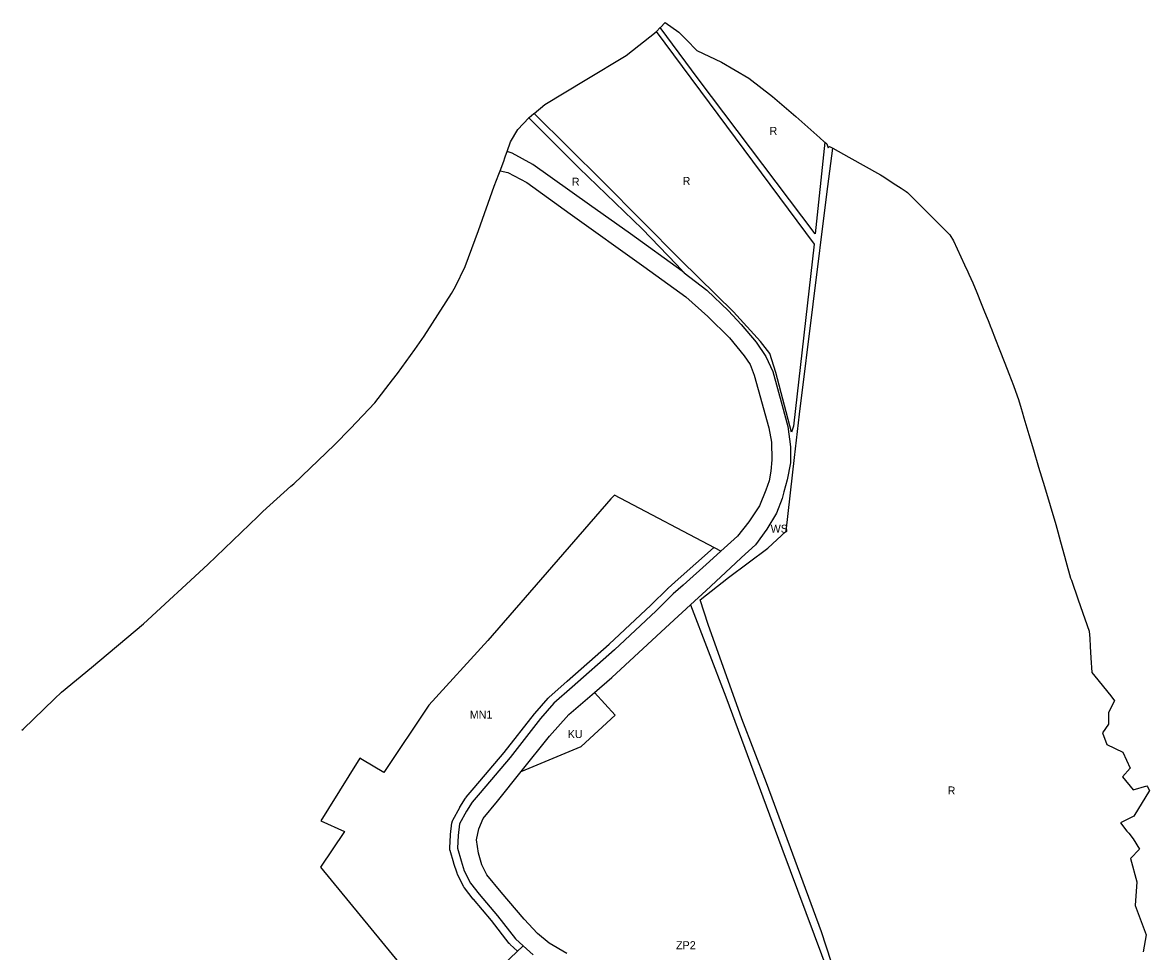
# Model space of a CAD drawing. Extents: x 7435758 to 7439981, y 5550649 to 5554049.
# Drawn here: x 7439107 to 7439840, y 5553445 to 5554049 of the extents above; entities that cross this region are included whole.
import ezdxf

# ---------------------------------------------------------------- set-up
doc = ezdxf.new("R2010")
doc.units = 0
for name, color, linetype in [('linie_rozgraniczające', 7, 'Continuous'), ('linie_zabudowy_nieprzekraczalne', 7, 'Continuous'), ('oznaczenia_przeznaczen', 7, 'Continuous')]:
    doc.layers.add(name, color=color, linetype=linetype)

msp = doc.modelspace()

# ---------------------------------------------------------------- linework, layer by layer
at = {"layer": 'linie_rozgraniczające'}
for p, q in [((7439519.4, 5554043.4), (7439521.89, 5554045.92)), ((7439521.89, 5554045.92), (7439521.96, 5554045.99)), ((7439546.56, 5554012.59), (7439521.89, 5554045.92)), ((7439521.96, 5554045.99), (7439525.14, 5554049.18)), ((7439525.14, 5554049.18), (7439533.95, 5554042.82)), ((7439499.63, 5554027.77), (7439519.15, 5554043.21)), ((7439519.15, 5554043.21), (7439519.29, 5554043.32)), ((7439519.29, 5554043.32), (7439519.4, 5554043.4)), ((7439519.29, 5554043.32), (7439621.8, 5553905.08)), ((7439533.95, 5554042.82), (7439538.84, 5554037.85)), ((7439538.84, 5554037.85), (7439545.59, 5554030.97)), ((7439545.59, 5554030.97), (7439561.7, 5554023.33)), ((7439473.16, 5554011.71), (7439499.63, 5554027.77)), ((7439561.7, 5554023.33), (7439579.49, 5554012.9)), ((7439446.82, 5553995.88), (7439473.16, 5554011.71)), ((7439622.59, 5553911.85), (7439546.56, 5554012.59)), ((7439579.49, 5554012.9), (7439594.73, 5554001.11)), ((7439594.73, 5554001.11), (7439609.96, 5553988.05)), ((7439439.82, 5553990.08), (7439446.82, 5553995.88)), ((7439429.27, 5553979.59), (7439436.46, 5553987.29)), ((7439436.46, 5553987.29), (7439436.49, 5553987.32)), ((7439436.46, 5553987.29), (7439469.19, 5553954.53)), ((7439436.49, 5553987.32), (7439436.68, 5553987.47)), ((7439436.68, 5553987.47), (7439439.73, 5553990.01)), ((7439439.73, 5553990.01), (7439439.82, 5553990.08)), ((7439484.6, 5553945.76), (7439439.82, 5553990.08)), ((7439609.96, 5553988.05), (7439617.71, 5553981.16)), ((7439424.63, 5553971.66), (7439429.27, 5553979.59)), ((7439617.71, 5553981.16), (7439625.47, 5553974.27)), ((7439422.39, 5553965.32), (7439424.63, 5553971.66)), ((7439628.73, 5553971.37), (7439622.59, 5553911.85)), ((7439625.47, 5553974.27), (7439628.49, 5553971.59)), ((7439628.49, 5553971.59), (7439628.73, 5553971.37)), ((7439628.73, 5553971.37), (7439630.05, 5553970.2)), ((7439421.38, 5553962.48), (7439422.39, 5553965.32)), ((7439425.72, 5553964.3), (7439422.39, 5553965.32)), ((7439439.05, 5553956.76), (7439425.72, 5553964.3)), ((7439630.05, 5553970.2), (7439630.97, 5553967.79)), ((7439630.05, 5553937.66), (7439634.03, 5553967.46)), ((7439630.97, 5553967.79), (7439631.91, 5553968.65)), ((7439631.91, 5553968.65), (7439634.03, 5553967.46)), ((7439634.03, 5553967.46), (7439644.42, 5553961.63)), ((7439417.73, 5553952.83), (7439420.11, 5553959.07)), ((7439420.11, 5553959.07), (7439420.94, 5553961.24)), ((7439420.94, 5553961.24), (7439421.38, 5553962.48)), ((7439475.93, 5553930.52), (7439439.05, 5553956.76)), ((7439644.42, 5553961.63), (7439664.95, 5553950.11)), ((7439413.89, 5553942.79), (7439416.9, 5553950.66)), ((7439416.9, 5553950.66), (7439417.73, 5553952.83)), ((7439417.73, 5553952.83), (7439422.85, 5553951.68)), ((7439422.85, 5553951.68), (7439435.1, 5553945.14)), ((7439469.19, 5553954.53), (7439510.12, 5553915.08)), ((7439664.95, 5553950.11), (7439667.1, 5553948.9)), ((7439403.68, 5553913.88), (7439413.89, 5553942.79)), ((7439435.1, 5553945.14), (7439463.28, 5553924.67)), ((7439535.22, 5553894.66), (7439484.6, 5553945.76)), ((7439667.1, 5553948.9), (7439673.33, 5553944.76)), ((7439673.33, 5553944.76), (7439678.47, 5553941.35)), ((7439612.46, 5553794.49), (7439630.05, 5553937.66)), ((7439678.47, 5553941.35), (7439681.73, 5553939.18)), ((7439681.73, 5553939.18), (7439682.57, 5553938.63)), ((7439682.57, 5553938.63), (7439684.76, 5553936.42)), ((7439684.76, 5553936.42), (7439691.39, 5553929.78)), ((7439502.48, 5553911.8), (7439475.93, 5553930.52)), ((7439691.39, 5553929.78), (7439694.7, 5553926.47)), ((7439463.28, 5553924.67), (7439511.29, 5553890.41)), ((7439694.7, 5553926.47), (7439710.07, 5553911.06)), ((7439395.12, 5553890.51), (7439403.68, 5553913.88)), ((7439510.12, 5553915.08), (7439532.32, 5553891.88)), ((7439536.02, 5553887.38), (7439502.48, 5553911.8)), ((7439710.07, 5553911.06), (7439712.48, 5553907.19)), ((7439712.48, 5553907.19), (7439719.66, 5553891.52)), ((7439621.8, 5553905.08), (7439608.35, 5553786.71)), ((7439388.8, 5553877.51), (7439395.12, 5553890.51)), ((7439532.32, 5553891.88), (7439537.31, 5553886.39)), ((7439569.55, 5553860.97), (7439535.22, 5553894.66)), ((7439719.66, 5553891.52), (7439721.74, 5553887.01)), ((7439511.29, 5553890.41), (7439538.4, 5553870.68)), ((7439537.31, 5553886.39), (7439536.02, 5553887.38)), ((7439537.31, 5553886.39), (7439552.15, 5553875.01)), ((7439721.74, 5553887.01), (7439722.41, 5553885.54)), ((7439722.41, 5553885.54), (7439725.04, 5553879.79)), ((7439386.28, 5553872.98), (7439388.8, 5553877.51)), ((7439725.04, 5553879.79), (7439727.58, 5553873.54)), ((7439373.74, 5553853.58), (7439386.28, 5553872.98)), ((7439538.4, 5553870.68), (7439552.72, 5553857.97)), ((7439552.15, 5553875.01), (7439566.11, 5553861.64)), ((7439727.58, 5553873.54), (7439730.41, 5553866.54)), ((7439566.11, 5553861.64), (7439574.54, 5553852.87)), ((7439730.41, 5553866.54), (7439732.68, 5553860.93)), ((7439552.72, 5553857.97), (7439566.82, 5553844.22)), ((7439586.98, 5553841.83), (7439569.55, 5553860.97)), ((7439732.68, 5553860.93), (7439734.35, 5553856.81)), ((7439734.35, 5553856.81), (7439734.96, 5553855.31)), ((7439734.96, 5553855.31), (7439736.77, 5553850.85)), ((7439368.39, 5553845.29), (7439373.74, 5553853.58)), ((7439574.54, 5553852.87), (7439584.13, 5553841.28)), ((7439736.77, 5553850.85), (7439736.95, 5553850.38)), ((7439736.95, 5553850.38), (7439739.81, 5553843.08)), ((7439362.27, 5553836.63), (7439368.39, 5553845.29)), ((7439566.82, 5553844.22), (7439576.41, 5553832.37)), ((7439584.13, 5553841.28), (7439590.5, 5553831.9)), ((7439592.97, 5553833.92), (7439586.98, 5553841.83)), ((7439739.81, 5553843.08), (7439742.22, 5553836.88)), ((7439351.15, 5553820.9), (7439362.27, 5553836.63)), ((7439576.41, 5553832.37), (7439580.29, 5553826.79)), ((7439590.5, 5553831.9), (7439595.06, 5553822.18)), ((7439597.01, 5553821.68), (7439592.97, 5553833.92)), ((7439742.22, 5553836.88), (7439745.8, 5553827.73)), ((7439580.29, 5553826.79), (7439582.91, 5553819.87)), ((7439745.8, 5553827.73), (7439748.36, 5553821.01)), ((7439347.92, 5553816.72), (7439351.15, 5553820.9)), ((7439582.91, 5553819.87), (7439585.51, 5553810.47)), ((7439595.06, 5553822.18), (7439601.03, 5553800.16)), ((7439607.09, 5553782.76), (7439597.01, 5553821.68)), ((7439748.36, 5553821.01), (7439751.4, 5553813.02)), ((7439336.46, 5553801.91), (7439347.92, 5553816.72)), ((7439585.51, 5553810.47), (7439592.51, 5553785.49)), ((7439751.4, 5553813.02), (7439753.88, 5553806.49)), ((7439753.88, 5553806.49), (7439754.64, 5553803.98)), ((7439754.64, 5553803.98), (7439756.4, 5553798.06)), ((7439320.65, 5553785.12), (7439336.46, 5553801.91)), ((7439601.03, 5553800.16), (7439604.71, 5553786.5)), ((7439756.4, 5553798.06), (7439757.05, 5553795.89)), ((7439757.05, 5553795.89), (7439758.17, 5553792.12)), ((7439609, 5553766.36), (7439612.46, 5553794.49)), ((7439758.17, 5553792.12), (7439761.41, 5553781.26)), ((7439310.14, 5553774.46), (7439320.65, 5553785.12)), ((7439592.51, 5553785.49), (7439594.19, 5553776.18)), ((7439604.71, 5553786.5), (7439606.55, 5553773.29)), ((7439608.35, 5553786.71), (7439607.09, 5553782.76)), ((7439761.41, 5553781.26), (7439764.41, 5553771.18)), ((7439283.64, 5553749.23), (7439310.14, 5553774.46)), ((7439594.19, 5553776.18), (7439594.4, 5553764.73)), ((7439606.55, 5553773.29), (7439606.45, 5553762.87)), ((7439603.68, 5553718.48), (7439609, 5553766.36)), ((7439764.41, 5553771.18), (7439767.7, 5553760.1)), ((7439594.4, 5553764.73), (7439593.65, 5553757.4)), ((7439606.45, 5553762.87), (7439604.3, 5553751.84)), ((7439767.7, 5553760.1), (7439771.48, 5553747.34)), ((7439593.65, 5553757.4), (7439592.6, 5553751.11)), ((7439604.3, 5553751.84), (7439602.24, 5553743.95)), ((7439263.63, 5553731.15), (7439281.86, 5553747.62)), ((7439281.86, 5553747.62), (7439283.64, 5553749.23)), ((7439590.51, 5553745.03), (7439586.36, 5553734.84)), ((7439592.6, 5553751.11), (7439590.51, 5553745.03)), ((7439771.48, 5553747.34), (7439775.22, 5553735.04)), ((7439489.79, 5553739.37), (7439409.89, 5553647.18)), ((7439492.1, 5553741.8), (7439489.79, 5553739.37)), ((7439561.24, 5553705.31), (7439492.1, 5553741.8)), ((7439601.14, 5553739.73), (7439597.49, 5553730.08)), ((7439602.24, 5553743.95), (7439601.14, 5553739.73)), ((7439260.4, 5553728.02), (7439263.63, 5553731.15)), ((7439586.36, 5553734.84), (7439579.49, 5553724.4)), ((7439597.49, 5553730.08), (7439591.15, 5553719.66)), ((7439775.22, 5553735.04), (7439778.96, 5553722.72)), ((7439227.86, 5553696.6), (7439260.4, 5553728.02)), ((7439579.49, 5553724.4), (7439572.05, 5553715.24)), ((7439778.96, 5553722.72), (7439780.27, 5553717.91)), ((7439572.05, 5553715.24), (7439561.24, 5553705.31)), ((7439591.15, 5553719.66), (7439583.74, 5553709.47)), ((7439591.73, 5553707.36), (7439603.68, 5553718.48)), ((7439780.27, 5553717.91), (7439782.01, 5553711.49)), ((7439566.28, 5553688.26), (7439591.73, 5553707.36)), ((7439583.74, 5553709.47), (7439574.72, 5553701.18)), ((7439782.01, 5553711.49), (7439784.56, 5553702.05)), ((7439561.24, 5553705.31), (7439553.97, 5553698.62)), ((7439574.72, 5553701.18), (7439570.69, 5553697.48)), ((7439784.56, 5553702.05), (7439785.45, 5553698.93)), ((7439186.11, 5553658.17), (7439227.86, 5553696.6)), ((7439553.97, 5553698.62), (7439536.7, 5553683.26)), ((7439570.69, 5553697.48), (7439551.61, 5553679.77)), ((7439785.45, 5553698.93), (7439788.59, 5553687.91)), ((7439547.73, 5553673.68), (7439566.28, 5553688.26)), ((7439788.59, 5553687.91), (7439789.05, 5553686.56)), ((7439789.05, 5553686.56), (7439793.52, 5553673.75)), ((7439536.7, 5553683.26), (7439530.34, 5553677.61)), ((7439551.61, 5553679.77), (7439541.46, 5553670.41)), ((7439530.34, 5553677.61), (7439519.2, 5553666.61)), ((7439552.99, 5553657.6), (7439547.73, 5553673.68)), ((7439793.52, 5553673.75), (7439797.82, 5553661.37)), ((7439519.2, 5553666.61), (7439492.09, 5553641.28)), ((7439528.14, 5553658.11), (7439541.46, 5553670.41)), ((7439541.46, 5553670.41), (7439564.47, 5553610.58)), ((7439152.26, 5553629.66), (7439186.11, 5553658.17)), ((7439490.48, 5553623.25), (7439528.14, 5553658.11)), ((7439574.79, 5553596.29), (7439552.99, 5553657.6)), ((7439797.82, 5553661.37), (7439800.63, 5553653.31)), ((7439800.63, 5553653.31), (7439800.94, 5553648.63)), ((7439409.89, 5553647.18), (7439371.55, 5553605.23)), ((7439800.94, 5553648.63), (7439801.27, 5553643.43)), ((7439801.27, 5553643.43), (7439801.77, 5553635.91)), ((7439492.09, 5553641.28), (7439464.69, 5553616.99)), ((7439801.77, 5553635.91), (7439802.39, 5553626.44)), ((7439132.68, 5553613.63), (7439152.26, 5553629.66)), ((7439479.18, 5553613.51), (7439490.48, 5553623.25)), ((7439802.39, 5553626.44), (7439804.22, 5553624.15)), ((7439804.22, 5553624.15), (7439814.65, 5553611.19)), ((7439128.2, 5553609.32), (7439132.68, 5553613.63)), ((7439464.69, 5553616.99), (7439452.74, 5553606.48)), ((7439462.55, 5553599.19), (7439479.18, 5553613.51)), ((7439492.56, 5553598.65), (7439479.18, 5553613.51)), ((7439107.81, 5553589.71), (7439128.2, 5553609.32)), ((7439371.55, 5553605.23), (7439342.23, 5553561.44)), ((7439452.74, 5553606.48), (7439444.03, 5553596.49)), ((7439564.47, 5553610.58), (7439600.88, 5553512.3)), ((7439817.1, 5553608.12), (7439813.14, 5553600.37)), ((7439814.65, 5553611.19), (7439817.1, 5553608.12)), ((7439449.97, 5553585.01), (7439462.55, 5553599.19)), ((7439470.39, 5553578.44), (7439492.56, 5553598.65)), ((7439813.14, 5553600.37), (7439813.13, 5553592.82)), ((7439444.03, 5553596.49), (7439424.22, 5553571.2)), ((7439591.01, 5553554.78), (7439574.79, 5553596.29)), ((7439813.13, 5553592.82), (7439809.25, 5553587.26)), ((7439107, 5553588.88), (7439107.81, 5553589.71)), ((7439431.48, 5553562), (7439449.97, 5553585.01)), ((7439809.25, 5553587.26), (7439812.03, 5553579.54)), ((7439431.48, 5553562), (7439470.39, 5553578.44)), ((7439812.03, 5553579.54), (7439822.39, 5553574.7)), ((7439326.58, 5553570.84), (7439306.26, 5553538.01)), ((7439328.41, 5553569.72), (7439326.58, 5553570.84)), ((7439328.43, 5553569.76), (7439328.41, 5553569.72)), ((7439342.23, 5553561.44), (7439328.43, 5553569.76)), ((7439424.22, 5553571.2), (7439404.84, 5553548.27)), ((7439822.39, 5553574.7), (7439827.21, 5553564.27)), ((7439416, 5553542.74), (7439431.48, 5553562)), ((7439827.21, 5553564.27), (7439822.33, 5553558.59)), ((7439626.65, 5553457.88), (7439591.01, 5553554.78)), ((7439822.33, 5553558.59), (7439829.2, 5553550.19)), ((7439404.84, 5553548.27), (7439399.62, 5553542.07)), ((7439829.2, 5553550.19), (7439838.14, 5553552.83)), ((7439839.8, 5553549.82), (7439829.68, 5553533.06)), ((7439838.14, 5553552.83), (7439838.56, 5553552.09)), ((7439838.56, 5553552.09), (7439839.8, 5553549.82)), ((7439399.62, 5553542.07), (7439395.95, 5553536.19)), ((7439406.82, 5553531.42), (7439416, 5553542.74)), ((7439306.26, 5553538.01), (7439301.35, 5553530.1)), ((7439395.95, 5553536.19), (7439391.46, 5553528.07)), ((7439829.68, 5553533.06), (7439820.98, 5553528.76)), ((7439301.35, 5553530.1), (7439316.55, 5553523.11)), ((7439391.46, 5553528.07), (7439390.47, 5553520.47)), ((7439402.43, 5553517.7), (7439403.96, 5553524.8)), ((7439403.96, 5553524.8), (7439406.82, 5553531.42)), ((7439820.98, 5553528.76), (7439825.2, 5553523.35)), ((7439316.55, 5553523.11), (7439301.05, 5553499.96)), ((7439390.47, 5553520.47), (7439390.02, 5553512.12)), ((7439403.69, 5553509.03), (7439402.43, 5553517.7)), ((7439825.2, 5553523.35), (7439826.34, 5553521.88)), ((7439826.34, 5553521.88), (7439829.19, 5553518.22)), ((7439829.19, 5553518.22), (7439833.3, 5553511.67)), ((7439390.02, 5553512.12), (7439392.44, 5553503.88)), ((7439600.88, 5553512.3), (7439637.66, 5553413.68)), ((7439833.3, 5553511.67), (7439827.54, 5553505.52)), ((7439392.44, 5553503.88), (7439394.52, 5553497.46)), ((7439405.83, 5553501.3), (7439403.69, 5553509.03)), ((7439827.54, 5553505.52), (7439831.65, 5553490.32)), ((7439301.05, 5553499.96), (7439384, 5553398.96)), ((7439394.52, 5553497.46), (7439398.49, 5553489.54)), ((7439409.21, 5553494.93), (7439405.83, 5553501.3)), ((7439398.49, 5553489.54), (7439404.26, 5553482.22)), ((7439418.53, 5553483.58), (7439409.21, 5553494.93)), ((7439831.65, 5553490.32), (7439830.52, 5553474.84)), ((7439404.26, 5553482.22), (7439416.16, 5553468.25)), ((7439433.31, 5553465.95), (7439418.53, 5553483.58)), ((7439830.52, 5553474.84), (7439837.74, 5553455.94)), ((7439416.16, 5553468.25), (7439427.7, 5553453.35)), ((7439442.02, 5553456.67), (7439433.31, 5553465.95)), ((7439427.7, 5553453.35), (7439432.82, 5553448.74)), ((7439449.57, 5553450.46), (7439442.02, 5553456.67)), ((7439636.99, 5553425.88), (7439626.65, 5553457.88)), ((7439837.74, 5553455.94), (7439835.78, 5553444.79)), ((7439411.84, 5553428.79), (7439432.82, 5553448.74)), ((7439432.82, 5553448.74), (7439439.32, 5553442.88)), ((7439461.17, 5553443.77), (7439449.57, 5553450.46))]:
    msp.add_line(p, q, dxfattribs=at)
at = {"layer": 'linie_zabudowy_nieprzekraczalne'}
for points in [[(7439533.56, 5553687.12), (7439556.41, 5553707.48)], [(7439429.19, 5553445.28), (7439424.35, 5553449.64), (7439424.31, 5553449.68), (7439424.08, 5553449.9), (7439423.86, 5553450.15), (7439423.75, 5553450.29), (7439412.27, 5553465.1), (7439400.45, 5553478.98), (7439400.42, 5553479.02), (7439400.33, 5553479.13), (7439394.57, 5553486.45), (7439394.45, 5553486.6), (7439394.27, 5553486.87), (7439394.1, 5553487.15), (7439394.02, 5553487.3), (7439390.06, 5553495.21), (7439389.99, 5553495.36), (7439389.86, 5553495.66), (7439389.77, 5553495.91), (7439387.69, 5553502.34), (7439387.67, 5553502.39), (7439387.64, 5553502.47), (7439385.23, 5553510.71), (7439385.16, 5553510.95), (7439385.1, 5553511.27), (7439385.05, 5553511.59), (7439385.03, 5553511.92), (7439385.02, 5553512.24), (7439385.03, 5553512.38), (7439385.47, 5553520.74), (7439385.49, 5553520.92), (7439385.51, 5553521.12), (7439386.5, 5553528.71), (7439386.52, 5553528.84), (7439386.58, 5553529.16), (7439386.66, 5553529.48), (7439386.77, 5553529.79), (7439386.89, 5553530.09), (7439387.03, 5553530.39), (7439387.08, 5553530.48), (7439391.57, 5553538.61), (7439391.68, 5553538.8), (7439391.71, 5553538.84), (7439395.38, 5553544.72), (7439395.53, 5553544.95), (7439395.73, 5553545.21), (7439395.79, 5553545.29), (7439401.01, 5553551.49), (7439401.02, 5553551.5), (7439420.34, 5553574.36), (7439440.1, 5553599.57), (7439440.14, 5553599.63), (7439440.26, 5553599.77), (7439448.97, 5553609.76), (7439449.07, 5553609.87), (7439449.3, 5553610.1), (7439449.44, 5553610.23), (7439461.37, 5553620.73), (7439488.73, 5553644.98), (7439515.73, 5553670.21), (7439526.83, 5553681.16), (7439526.89, 5553681.23), (7439527.02, 5553681.34), (7439533.56, 5553687.12)]]:
    msp.add_lwpolyline(points, dxfattribs=at)

# ---------------------------------------------------------------- texts
at = {"layer": 'oznaczenia_przeznaczen'}
for s, p in [('R', (7439592.9, 5553976.11)), ('R', (7439464.43, 5553943.04)), ('R', (7439536.41, 5553943.54)), ('WS', (7439593.62, 5553717.36)), ('MN1', (7439398.07, 5553596.53)), ('KU', (7439461.76, 5553583.83)), ('R', (7439708.64, 5553547.13)), ('ZP2', (7439532.15, 5553446.51))]:
    msp.add_text(s, height=5.2, dxfattribs=at).set_placement(p)

doc.saveas('drawing.dxf')
